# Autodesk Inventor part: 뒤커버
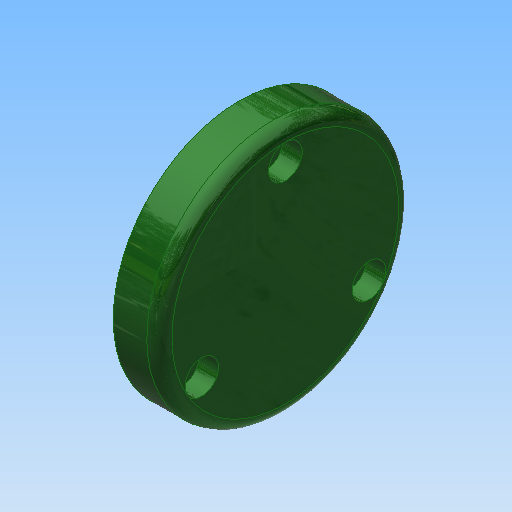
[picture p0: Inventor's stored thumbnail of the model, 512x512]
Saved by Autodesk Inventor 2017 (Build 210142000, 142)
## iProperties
Created: 2015-11
Part Number: 뒤커버
Material: 알루미늄 6061
Document SubType Name: Modeling
Designer: mduedu
Density: 1 g/cm^3
Appearance: 매끄러움 - 짙은 산림 녹색
Author: mduedu
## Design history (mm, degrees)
sketch "스케치5"
  geometry: C1 r 30 at (0, 0); 2 further points
  constraints: 2 coincident, 1 centre point
  dimensions: "d66" = 60 diameter of C1
extrude "돌출2" new body sketch "스케치5" distance "d67" = 11; taper "d68" = 0 deg
sketch "스케치6"
  geometry: C1 r 16 at (0, 0); 1 further point
  constraints: 1 centre point, 1 coincident
  dimensions: "d69" = 32 diameter of C1
extrude "돌출3" join sketch "스케치6" distance "d70" = 3; taper "d71" = 0 deg
hole "구멍5" diameter "d74" = 27; stored, may be unused: countersink angle "d78" = 90 deg, drill point angle "d80" = 0 deg; dims "d75" = 6, "d76" = 4, "d77" = 2, "d79" = 10, "d100" = 10, "d101" = 10
fillet "모깎기8" dims "d82" = 3
fillet "모깎기9" dims "d83" = 3
fillet "모깎기10" dims "d84" = 0.3
sketch "스케치7" dims "d85" = 46
  geometry: 3 further points
  constraints: 2 vertical alignment, 1 coincident, 2 other
hole "구멍6" sketch "스케치7" at (0, 23) diameter "d86" = 4.5; stored, may be unused: countersink angle "d90" = 90 deg, drill point angle "d92" = 0 deg; dims "d87" = 6, "d88" = 8, "d89" = 4.6, "d91" = 10
node "솔리드2"
pattern_circular "원형 패턴3" dims angle "d94" = 360 deg
